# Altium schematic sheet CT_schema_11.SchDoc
size 387 x 385 mm
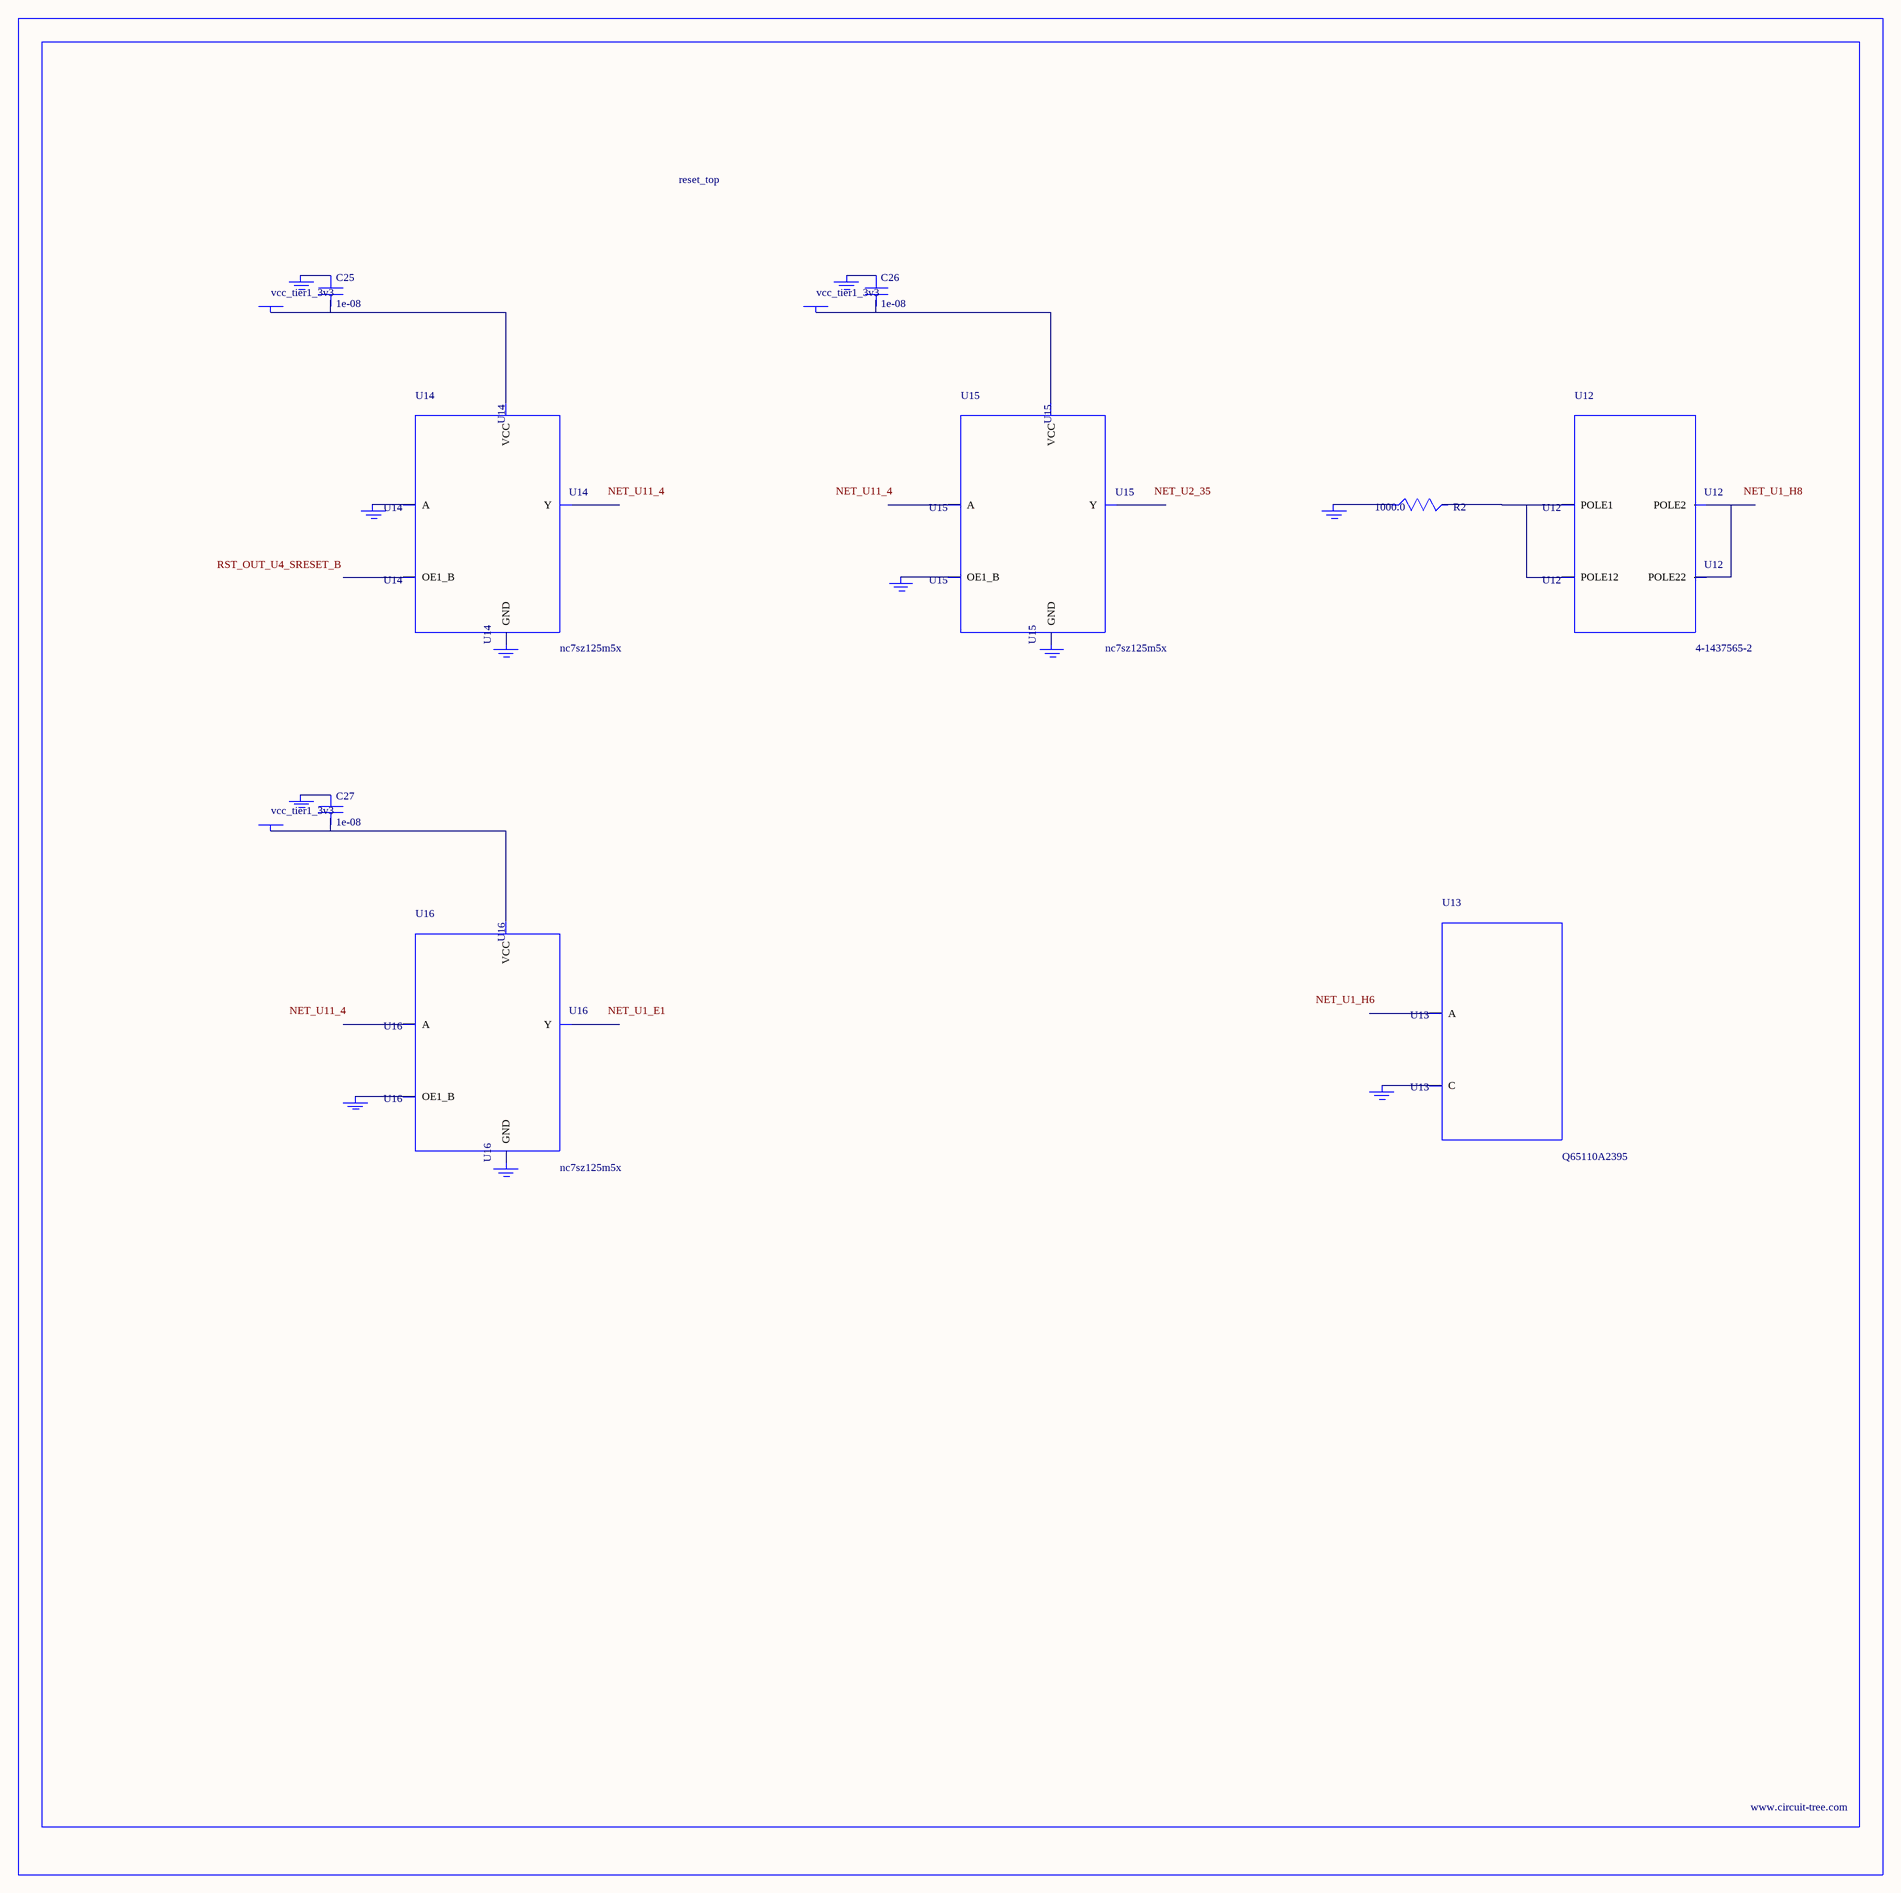
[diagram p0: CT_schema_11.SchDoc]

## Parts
BORDER10  (no value)
C25  1e-08  [C0402]
C26  1e-08  [C0402]
C27  1e-08  [C0402]
GND_INSTANCE_10_0  (no value)
GND_INSTANCE_10_1  (no value)
GND_INSTANCE_10_2  (no value)
GND_INSTANCE_10_3  (no value)
GND_INSTANCE_10_4  (no value)
GND_INSTANCE_10_5  (no value)
GND_INSTANCE_10_6  (no value)
GND_INSTANCE_10_7  (no value)
GND_INSTANCE_10_8  (no value)
GND_INSTANCE_10_9  (no value)
GND_INSTANCE_10_10  (no value)
POWER_INSTANCE_10_0  vcc_tier1_3v3
POWER_INSTANCE_10_1  vcc_tier1_3v3
POWER_INSTANCE_10_2  vcc_tier1_3v3
R2  1000.0  [R0603]
U12  4-1437565-2  [SW_4-1437565-2]
U13  Q65110A2395  [LGM67K-G1J2-24-Z]
U14  nc7sz125m5x  [NC7SZ125M5X]
U15  nc7sz125m5x  [NC7SZ125M5X]
U16  nc7sz125m5x  [NC7SZ125M5X]

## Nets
NetC25_1: C25.1 GND_INSTANCE_10_2.0(GND)
NetC25_2: C25.2 POWER_INSTANCE_10_0.0(PWR) U14.5(VCC)
NetC26_1: C26.1 GND_INSTANCE_10_5.0(GND)
NetC26_2: C26.2 POWER_INSTANCE_10_1.0(PWR) U15.5(VCC)
NetC27_1: C27.1 GND_INSTANCE_10_8.0(GND)
NetC27_2: C27.2 POWER_INSTANCE_10_2.0(PWR) U16.5(VCC)
NetGND_INSTANCE_10_0_0: GND_INSTANCE_10_0.0(GND) R2.1
NetGND_INSTANCE_10_1_0: GND_INSTANCE_10_1.0(GND) U13.C
NetGND_INSTANCE_10_3_0: GND_INSTANCE_10_3.0(GND) U14.2(A)
NetGND_INSTANCE_10_4_0: GND_INSTANCE_10_4.0(GND) U14.3(GND)
NetGND_INSTANCE_10_6_0: GND_INSTANCE_10_6.0(GND) U15.1(OE1_B)
NetGND_INSTANCE_10_7_0: GND_INSTANCE_10_7.0(GND) U15.3(GND)
NetGND_INSTANCE_10_9_0: GND_INSTANCE_10_9.0(GND) U16.1(OE1_B)
NetGND_INSTANCE_10_10_0: GND_INSTANCE_10_10.0(GND) U16.3(GND)
NetR2_2: R2.2 U12.1(POLE1) U12.2(POLE12)
NetU12_3: U12.3(POLE2) U12.4(POLE22)

Not connected (* = marked no-connect by the designer): U13 A; U14 1(OE1_B) 4(Y); U15 2(A) 4(Y); U16 2(A) 4(Y)

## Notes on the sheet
- Labels drawn without touching a wire or pin: NET_U1_E1, NET_U1_H6, NET_U1_H8, NET_U2_35, NET_U11_4, RST_OUT_U4_SRESET_B

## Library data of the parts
BORDER10 = BORDER_PAGE10
C25-C27 = C0402C103K3RAC
GND_INSTANCE_10_0-GND_INSTANCE_10_10 = GND
POWER_INSTANCE_10_0-POWER_INSTANCE_10_2 = PWR
R2 = RC0603JR-071KL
